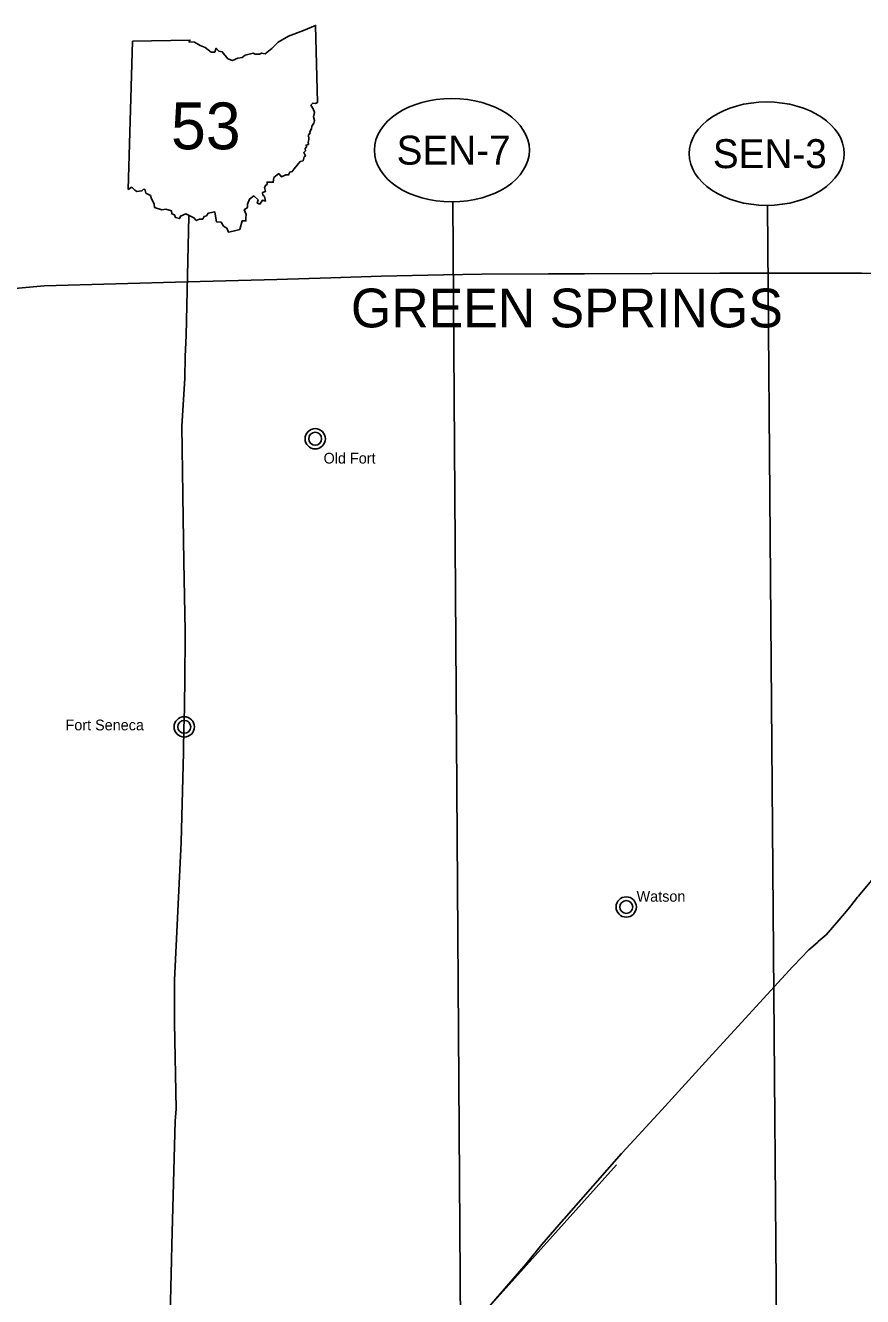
# Model space of a CAD drawing. Extents: x 0 to 882, y 0 to 440.
# Drawn here: x 300 to 381, y 237.6 to 360.5 of the extents above; entities that cross this region are included whole.
import ezdxf

# ---------------------------------------------------------------- set-up
doc = ezdxf.new("R2010")
doc.units = 0
for name, color, linetype in [('DV_X_Corp_Line', 7, 'Continuous'), ('GM_X_Corporation_Text', 7, 'Continuous'), ('GM_X_County', 7, 'Continuous'), ('GM_X_State_Route', 7, 'Continuous'), ('PV_P_Text', 7, 'Continuous'), ('RD_P_Fence', 7, 'Continuous'), ('SH_Data', 7, 'Continuous')]:
    doc.layers.add(name, color=color, linetype=linetype)

msp = doc.modelspace()

# ---------------------------------------------------------------- linework, layer by layer
at = {"layer": 'DV_X_Corp_Line'}
for centre, radius in [((328.03, 320.54), 0.982), ((328.03, 320.54), 0.623), ((315.36, 292.68), 0.982), ((315.36, 292.68), 0.623), ((358.13, 275.26), 0.982), ((358.13, 275.26), 0.623)]:
    msp.add_circle(centre, radius, dxfattribs=at)
at = {"layer": 'GM_X_County'}
msp.add_lwpolyline([(296.79, 334.89), (301.81, 335.33), (315.66, 335.72), (324.32, 335.94), (329.54, 336.1), (334.41, 336.25), (340.44, 336.39), (344.17, 336.46), (350.6, 336.5), (353.74, 336.5), (354.09, 336.5), (367.2, 336.56), (367.65, 336.56), (374.05, 336.54), (380.91, 336.56), (386.87, 336.47)], dxfattribs=at)
at = {"layer": 'GM_X_State_Route'}
for points in [[(315.21, 315.03), (315.21, 315.18), (315.13, 321.76), (315.42, 326.38), (315.46, 328.49), (315.56, 330.52), (315.79, 342.05)], [(315.4, 296.83), (315.45, 301.93), (315.33, 308.66), (315.21, 315.03), (315.21, 315.03)], [(315.28, 290.21), (315.3, 291.01), (315.32, 292.02), (315.33, 292.61), (315.35, 293.29), (315.35, 293.61), (315.37, 294.34), (315.37, 294.49), (315.38, 294.64), (315.39, 295.26), (315.4, 296.83)], [(313.98, 234.41), (313.98, 234.46), (314.14, 241.1), (314.16, 242.6), (314.49, 254.55), (314.58, 255.73), (314.42, 264.05), (314.41, 268.18), (315.07, 281.53), (315.28, 290.21)], [(380.59, 276.3), (382.18, 278.22)], [(376.71, 271.91), (377.46, 272.56), (378.69, 273.98), (379.6, 275.06), (379.86, 275.38), (380.52, 276.21), (380.59, 276.3)], [(374.32, 269.56), (375.8, 271.12), (376.66, 271.86), (376.71, 271.91)], [(357.72, 251.47), (358.12, 251.92), (361.58, 255.65), (366.12, 260.63), (374.23, 269.46), (374.32, 269.56)], [(352.12, 245.11), (357.67, 251.41), (357.72, 251.47)], [(348.44, 240.75), (349.96, 242.61), (352.06, 245.05), (352.12, 245.11)], [(333.52, 226.93), (334.3, 227.65), (336.15, 229.28), (338, 230.9), (338.98, 231.73), (340.18, 232.8), (342.65, 234.94), (343.59, 235.43), (343.96, 235.66), (344.25, 235.91), (348.44, 240.75)]]:
    msp.add_lwpolyline(points, dxfattribs=at)
at = {"layer": 'PV_P_Text'}
msp.add_line((309.94, 344.64), (310.34, 359), dxfattribs=at)
msp.add_line((309.94, 344.64), (310.34, 359), dxfattribs=at)
for points in [[(310.34, 359), (315.91, 359.09), (315.83, 358.92), (316.35, 358.88), (316.91, 358.58), (317.38, 358.38), (317.96, 357.93), (318.31, 357.93), (318.45, 358.31), (318.72, 358.02), (319.03, 357.97), (319.58, 357.28), (320.02, 357.13), (320.56, 357.36), (320.96, 357.4), (321.26, 357.64), (322.02, 357.84), (322.23, 357.72), (322.64, 357.74), (322.84, 357.83), (323.2, 357.75), (323.82, 358.27), (324.46, 358.89), (325.44, 359.47), (326.91, 360.02), (328.07, 360.51), (328.24, 353.06)], [(310.34, 359), (315.91, 359.09), (315.83, 358.92), (316.35, 358.88), (316.91, 358.58), (317.38, 358.38), (317.96, 357.93), (318.31, 357.93), (318.45, 358.31), (318.72, 358.02), (319.03, 357.97), (319.58, 357.28), (320.02, 357.13), (320.56, 357.36), (320.96, 357.4), (321.26, 357.64), (322.02, 357.84), (322.23, 357.72), (322.64, 357.74), (322.84, 357.83), (323.2, 357.75), (323.82, 358.27), (324.46, 358.89), (325.44, 359.47), (326.91, 360.02), (328.07, 360.51), (328.24, 353.06)], [(328.24, 353.06), (328.07, 352.95), (327.8, 353), (327.62, 352.79), (327.85, 352.44), (327.95, 352.08), (327.86, 351.67), (327.95, 351.33), (327.89, 351.05), (327.72, 350.78), (327.66, 350.51), (327.52, 350.23), (327.53, 350.07), (327.39, 349.95), (327.42, 349.48), (327.35, 349.22), (327.37, 349), (327.15, 348.94), (327.2, 348.76), (327.06, 348.62), (327.09, 348.37), (326.93, 348.22), (327.09, 347.9), (326.96, 347.8), (326.86, 347.42), (326.58, 347.35), (326.01, 346.65), (325.81, 346.39), (325.59, 346.32), (325.46, 346.05), (325.19, 346.05), (324.77, 345.86), (324.5, 346.19), (324.02, 345.8), (323.97, 345.35), (323.37, 345.36), (323.39, 345.14), (323.26, 345.07), (323.14, 344.85), (323.21, 344.44), (322.93, 344.34), (322.96, 344.11), (323.14, 343.96), (323.22, 343.52), (322.92, 343.61), (322.68, 343.23), (322.43, 343.32), (322.51, 343.64), (322.08, 344.02), (321.68, 343.71), (321.47, 343.22), (321.47, 342.89), (321.17, 342.69), (321.36, 342.22), (321.33, 341.9), (321.33, 341.6), (320.96, 341.61), (320.73, 340.78)], [(328.24, 353.06), (328.07, 352.95), (327.8, 353), (327.62, 352.79), (327.85, 352.44), (327.95, 352.08), (327.86, 351.67), (327.95, 351.33), (327.89, 351.05), (327.72, 350.78), (327.66, 350.51), (327.52, 350.23), (327.53, 350.07), (327.39, 349.95), (327.42, 349.48), (327.35, 349.22), (327.37, 349), (327.15, 348.94), (327.2, 348.76), (327.06, 348.62), (327.09, 348.37), (326.93, 348.22), (327.09, 347.9), (326.96, 347.8), (326.86, 347.42), (326.58, 347.35), (326.01, 346.65), (325.81, 346.39), (325.59, 346.32), (325.46, 346.05), (325.19, 346.05), (324.77, 345.86), (324.5, 346.19), (324.02, 345.8), (323.97, 345.35), (323.37, 345.36), (323.39, 345.14), (323.26, 345.07), (323.14, 344.85), (323.21, 344.44), (322.93, 344.34), (322.96, 344.11), (323.14, 343.96), (323.22, 343.52), (322.92, 343.61), (322.68, 343.23), (322.43, 343.32), (322.51, 343.64), (322.08, 344.02), (321.68, 343.71), (321.47, 343.22), (321.47, 342.89), (321.17, 342.69), (321.36, 342.22), (321.33, 341.9), (321.33, 341.6), (320.96, 341.61), (320.73, 340.78)], [(320.73, 340.78), (320.08, 340.63), (319.63, 340.53), (319.47, 340.91), (319.15, 341.1), (318.94, 341.48), (318.48, 341.53), (318.37, 342.05), (318.31, 342.47), (317.68, 342.37), (317.51, 342.11), (317.28, 342.04), (317.15, 341.78), (316.85, 341.76), (316.52, 341.64), (316.3, 341.89), (315.76, 342.15), (315.52, 342.28), (315.01, 342.07), (314.91, 341.83), (314.5, 341.94), (314.41, 342.21), (314.16, 342.29), (314.11, 342.58), (313.59, 342.73), (313.19, 342.67), (312.49, 342.9), (312.44, 343.27), (312.2, 343.73), (312.08, 344.05), (311.63, 344.29), (311.54, 344.67), (311.4, 344.66), (311.27, 344.51), (310.78, 344.44), (310.58, 344.59), (310.3, 344.86), (309.94, 344.64)], [(320.73, 340.78), (320.08, 340.63), (319.63, 340.53), (319.47, 340.91), (319.15, 341.1), (318.94, 341.48), (318.48, 341.53), (318.37, 342.05), (318.31, 342.47), (317.68, 342.37), (317.51, 342.11), (317.28, 342.04), (317.15, 341.78), (316.85, 341.76), (316.52, 341.64), (316.3, 341.89), (315.76, 342.15), (315.52, 342.28), (315.01, 342.07), (314.91, 341.83), (314.5, 341.94), (314.41, 342.21), (314.16, 342.29), (314.11, 342.58), (313.59, 342.73), (313.19, 342.67), (312.49, 342.9), (312.44, 343.27), (312.2, 343.73), (312.08, 344.05), (311.63, 344.29), (311.54, 344.67), (311.4, 344.66), (311.27, 344.51), (310.78, 344.44), (310.58, 344.59), (310.3, 344.86), (309.94, 344.64)]]:
    msp.add_lwpolyline(points, dxfattribs=at)
at = {"layer": 'RD_P_Fence'}
msp.add_lwpolyline([(320.32, 214.85), (336.15, 229.28), (342.65, 234.94), (344.25, 235.91), (357.18, 250.34)], dxfattribs=at)
at = {"layer": 'SH_Data'}
for p, q in [((341.34, 343.45), (342.09, 234.45)), ((371.8, 343.11), (372.8, 216.18))]:
    msp.add_line(p, q, dxfattribs=at)
for centre in [(341.26, 348.45), (371.72, 348.11)]:
    msp.add_ellipse(centre, major_axis=(7.5, 0), ratio=0.666667, dxfattribs=at)

# ---------------------------------------------------------------- texts
at = {"layer": 'DV_X_Corp_Line'}
for s, height, p in [('Old Fort', 1.042, (328.84, 318.14)), ('Fort Seneca', 1.0417, (303.87, 292.34)), ('Watson', 1.042, (359.13, 275.77))]:
    msp.add_text(s, height=height, rotation=0, dxfattribs=at).set_placement(p)
at = {"layer": 'GM_X_Corporation_Text'}
msp.add_text('GREEN SPRINGS', height=3.75, rotation=0, dxfattribs=at).set_placement((331.49, 331.31))
at = {"layer": 'PV_P_Text'}
msp.add_text('53', height=4.528, dxfattribs=at).set_placement((314.08, 348.53))
at = {"layer": 'SH_Data'}
for s, p in [('SEN-7', (335.91, 347.05)), ('SEN-3', (366.51, 346.71))]:
    msp.add_text(s, height=2.8, dxfattribs=at).set_placement(p)

doc.saveas('drawing.dxf')
